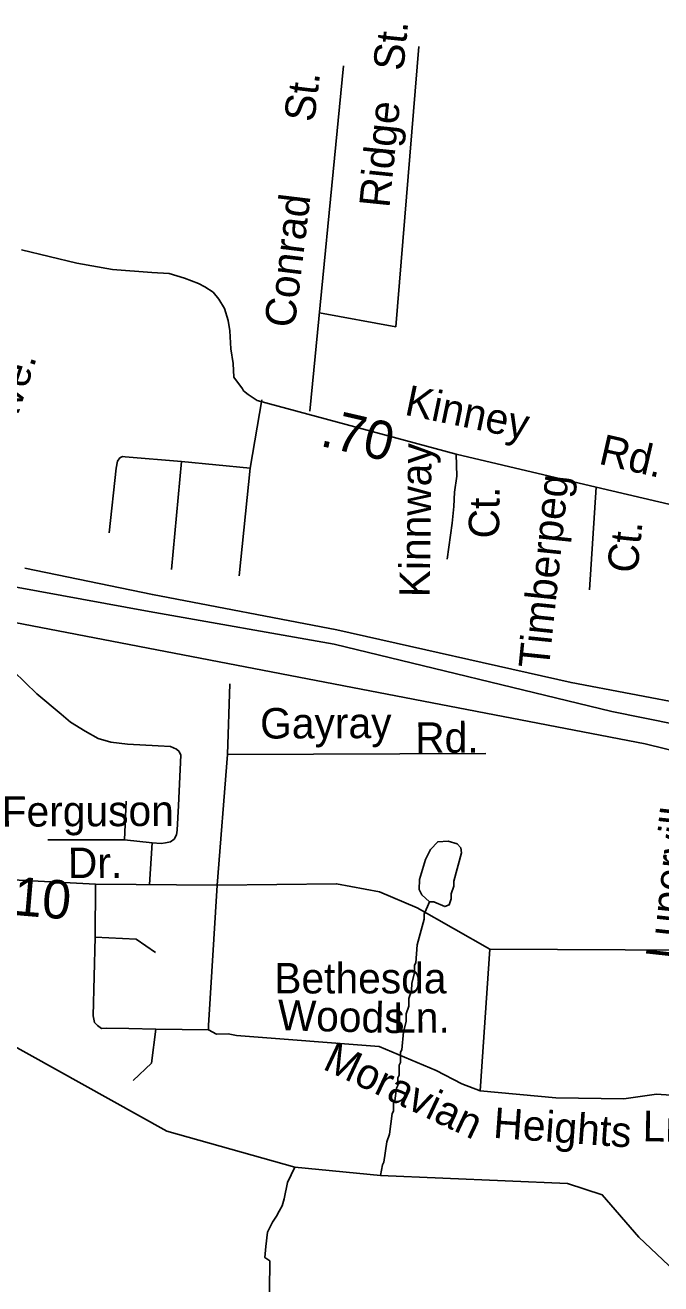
# Model space of a CAD drawing. Extents: x 1547597 to 1699558, y 810033 to 920809.
# Drawn here: x 1591291 to 1593272, y 847300 to 851225 of the extents above; entities that cross this region are included whole.
import ezdxf

# ---------------------------------------------------------------- set-up
doc = ezdxf.new("R2010")
doc.units = 0
for name, color, linetype in [('Exist Boundary Political City Limit New', 7, 'Continuous'), ('Exist Hydrographic Misc Water Feature', 7, 'Continuous'), ('Exist Road Non-System Type 51', 7, 'Continuous'), ('Exist Road Non-System Type 51 Label', 7, 'Continuous'), ('Exist Road Primary US Divided Attributed', 7, 'Continuous'), ('Exist Road Secondary Mileage Hundredths English Label', 7, 'Continuous'), ('Exist Road Secondary Type 51 Attributed', 7, 'Continuous'), ('Exist Road Secondary Type 51 Label', 7, 'Continuous'), ('Map Preparation Boundary City Limit Buffer Line', 7, 'Continuous')]:
    doc.layers.add(name, color=color, linetype=linetype)

msp = doc.modelspace()

# ---------------------------------------------------------------- linework, layer by layer
at = {"layer": 'Exist Boundary Political City Limit New'}
msp.add_lwpolyline([(1596904.9, 847270.3), (1596284, 847806.6), (1595748.2, 848233.1), (1595309.9, 848452.5), (1594414.4, 848690.8), (1593223.6, 848983.5), (1590507.7, 849506.1), (1589412.8, 849462.6)], dxfattribs=at)
at = {"layer": 'Exist Hydrographic Misc Water Feature'}
for points in [[(1592551.1, 848490.7), (1592565, 848490.6), (1592598.8, 848476.1), (1592613, 848481.9), (1592619.1, 848499.9), (1592619.3, 848515.9), (1592627.6, 848539.7), (1592627.8, 848555.7), (1592650.8, 848643.4), (1592649.1, 848659.4), (1592637.2, 848671.6), (1592609.3, 848679.9), (1592577.3, 848678.3), (1592554.9, 848654.6), (1592538.6, 848622.8), (1592519.9, 848561.1), (1592519.5, 848529.1), (1592527.3, 848513), (1592551.1, 848490.7)], [(1592551.1, 848490.7), (1592534.6, 848452.9), (1592534.4, 848436.9), (1592513.4, 848357.3), (1592508.8, 848301.3), (1592504.7, 848293.4), (1592504.4, 848269.4), (1592496.1, 848237.5), (1592495.8, 848213.5), (1592487.5, 848189.6), (1592487.2, 848165.6), (1592478.9, 848141.8), (1592478.7, 848117.8), (1592470.3, 848085.9), (1592465.5, 848030), (1592461.5, 848022.1), (1592461.1, 847990.1), (1592457, 847982.1), (1592456.6, 847950.1), (1592452.5, 847942.2), (1592452.3, 847918.2), (1592448.2, 847910.3), (1592443.7, 847870.4), (1592439.6, 847862.4), (1592439.3, 847838.4), (1592435.2, 847830.5), (1592426.5, 847766.6), (1592418.2, 847742.7), (1592409.5, 847678.9), (1592405.4, 847670.9), (1592399.1, 847637.2)], [(1593705.8, 847052.8), (1593390, 847269.6), (1593203.6, 847445.6), (1593089.8, 847577.5), (1592981.8, 847612.4), (1592399.1, 847637.2), (1592131.3, 847663.1), (1591732.4, 847775.4), (1591129.6, 848111.4)], [(1592032.8, 847046.5), (1592034.2, 847067.8), (1592038.3, 847075.8), (1592038.7, 847107.8), (1592042.8, 847115.7), (1592043.2, 847147.7), (1592047.3, 847155.7), (1592047.5, 847179.7), (1592051.6, 847187.6), (1592053.9, 847371.5), (1592038.6, 847381.7), (1592041.5, 847416), (1592046.4, 847460.7), (1592062.7, 847492.4), (1592074.5, 847511), (1592082.7, 847526.9), (1592092.8, 847543.1), (1592098.5, 847564.5), (1592108.5, 847615.9), (1592131.3, 847663.1)]]:
    msp.add_lwpolyline(points, dxfattribs=at)
at = {"layer": 'Exist Road Non-System Type 51'}
for p, q in [((1592446.2, 850284.4), (1592518.5, 851158.7)), ((1592283.5, 851098.4), (1592178.9, 850020.8)), ((1592446.2, 850284.4), (1592208.7, 850328.1)), ((1592029.4, 850056.7), (1591992.8, 849843.5)), ((1591778.8, 849864.5), (1591747.6, 849527.1)), ((1591992.8, 849843.5), (1591778.8, 849864.5)), ((1591992.8, 849843.5), (1591958.4, 849507.7)), ((1593070.6, 849783.9), (1593050.1, 849463.6)), ((1591921.7, 848950.6), (1591929, 849170.8)), ((1592739.9, 848343.9), (1592709.7, 847901.5))]:
    msp.add_line(p, q, dxfattribs=at)
for points in [[(1591778.8, 849864.5), (1591603, 849879), (1591595, 849879.2), (1591586.9, 849875.3), (1591578.7, 849865.5), (1591574.5, 849843.6), (1591553.6, 849641.7)], [(1592634.5, 849887.4), (1592636.4, 849818.5), (1592628.9, 849768.2), (1592626.8, 849723.7), (1592622.5, 849672), (1592606.6, 849559.6)], [(1591687.5, 848675.3), (1591714.8, 848673.1), (1591728.5, 848675.3), (1591744.4, 848677.6), (1591755.7, 848686.7), (1591762.6, 848700.4), (1591764.8, 848714), (1591769.4, 848791.4), (1591776.2, 848948.4), (1591771.7, 848959.7), (1591762.6, 848966.6), (1591744.4, 848975.7), (1591705.7, 848977.9), (1591610.2, 848982.5), (1591557.9, 848989.3), (1591519.3, 849000.7), (1591478.3, 849023.5), (1591432.8, 849050.8), (1591403.3, 849075.8), (1591328.2, 849139.5), (1591255.5, 849210)], [(1591889.9, 848543.4), (1591921.7, 848950.6), (1592727.4, 848953.7)], [(1591601.1, 848684.4), (1591605.7, 848805)], [(1591601.1, 848684.4), (1591362.3, 848684.4)], [(1591687.5, 848675.3), (1591601.1, 848684.4)], [(1591678.4, 848544.7), (1591687.5, 848675.3)], [(1591510.7, 848545.8), (1591509.1, 848381.1)], [(1591889.9, 848543.4), (1591862.6, 848105.6), (1591862.6, 848091.9), (1591887.6, 848078.3), (1591924.5, 848078.9), (1591950.4, 848074.5), (1592394.1, 848039.9)], [(1591509.1, 848381.1), (1591502.8, 848135), (1591507.5, 848114.6), (1591516.9, 848105.2), (1591529.5, 848095.8), (1591545.2, 848097.3), (1591614.1, 848095.8), (1591698.7, 848094.2)], [(1591509.1, 848381.1), (1591637.6, 848374.9), (1591697.1, 848332.5)], [(1591698.7, 848094.2), (1591684.6, 847987.6), (1591628.2, 847934.3)], [(1591698.7, 848094.2), (1591862.6, 848091.9)], [(1592709.7, 847901.5), (1592652, 847923.5), (1592572.4, 847964.7), (1592394.1, 848039.9)], [(1593483.1, 847875.6), (1593258.8, 847891.2), (1593157.2, 847877), (1592944.7, 847879.4), (1592709.7, 847901.5)]]:
    msp.add_lwpolyline(points, dxfattribs=at)
at = {"layer": 'Exist Road Primary US Divided Attributed'}
for points in [[(1590638.9, 849586.4), (1591678, 849396.8), (1592254.3, 849294.4), (1593119.7, 849084.6), (1593824, 848941.9), (1594286.9, 848867.3), (1594656.2, 848811), (1595128.1, 848723.1), (1595435.7, 848659.4), (1595944.6, 848547.4), (1596390, 848470.5), (1596495.3, 848448.6)], [(1596506.7, 848509.8), (1596372.9, 848534), (1596223.7, 848560.3), (1595962.3, 848607.8), (1595714.7, 848662.1), (1595389.3, 848736.9), (1595059.2, 848790.9), (1594838.5, 848830.9), (1594539.5, 848885.9), (1594246.7, 848937.3), (1593923.6, 848997.9), (1593737.1, 849034), (1592992.5, 849174.6), (1592262.7, 849338.8), (1591688, 849449.1), (1591290.1, 849531.1)]]:
    msp.add_lwpolyline(points, dxfattribs=at)
at = {"layer": 'Exist Road Secondary Type 51 Attributed'}
for points in [[(1591279.6, 850524.1), (1591452.6, 850482.1), (1591563.8, 850463.3), (1591686.6, 850453.2), (1591739.8, 850450.2), (1591787.5, 850435.5), (1591831.4, 850418.8), (1591851.2, 850408.6), (1591876.9, 850392.2), (1591894.7, 850369.9), (1591912.3, 850341.7), (1591923.8, 850303.4), (1591929.3, 850271.3), (1591932.4, 850215.4), (1591939.8, 850169.2), (1591941.2, 850127), (1591969.1, 850090.4), (1591972.3, 850084.8), (1591986.7, 850073.2), (1592014.3, 850054.5), (1592634.5, 849887.4), (1593070.6, 849783.9), (1593461.3, 849692.6)], [(1590993.6, 848572.6), (1591510.7, 848545.8), (1591889.9, 848543.4), (1592262.1, 848547.6), (1592395.8, 848522.5), (1592512.7, 848472.4), (1592739.9, 848343.9), (1593372.1, 848340.6), (1594984, 848241.4)]]:
    msp.add_lwpolyline(points, dxfattribs=at)
at = {"layer": 'Map Preparation Boundary City Limit Buffer Line'}
msp.add_lwpolyline([(1596904.9, 847270.3), (1596284, 847806.6), (1595748.2, 848233.1), (1595309.9, 848452.5), (1594414.4, 848690.8), (1593223.6, 848983.5), (1590507.7, 849506.1), (1589412.8, 849462.6)], dxfattribs=at)

# ---------------------------------------------------------------- texts
at = {"layer": 'Exist Road Non-System Type 51 Label'}
for s, rotation, p in [('St.', 84.1973, (1592469.8, 851080.2)), ('St.', 83.0766, (1592192.2, 850920.4)), ('Ridge', 84.1973, (1592426.4, 850653)), ('Conrad', 83.0766, (1592130.7, 850278.3)), ('Ave.', 71.7839, (1591249, 849947.2)), ('Kinnway', 89.2551, (1592552.2, 849440.3)), ('Timberpeg', 84.0792, (1592923.2, 849215)), ('Ct.', 89.2551, (1592768.2, 849623.5)), ('Ct.', 84.0792, (1593199.1, 849513.3)), ('Gayray', 0.2324, (1592023.8, 849000.1)), ('Rd.', 0.2324, (1592507.1, 848955.4)), ('Luperville', 83.8524, (1593319.5, 848309.5)), ('Ferguson', 0.2987, (1591218.3, 848725.1)), ('Dr.', 0.2944, (1591424.7, 848564.9)), ('Bethesda', 0.0147, (1592067.7, 848205.3)), ('Woods', 358.6039, (1592077.5, 848090.8)), ('Ln.', 0.3375, (1592438.2, 848082.4)), ('Moravian', 334.7401, (1592215.1, 847971.3)), ('Heights', 355.931, (1592748.1, 847755.3)), ('Ln.', 358.9243, (1593215.1, 847744.7))]:
    msp.add_text(s, height=95, rotation=rotation, dxfattribs=at).set_placement(p)
at = {"layer": 'Exist Road Secondary Mileage Hundredths English Label'}
for s, rotation, p in [('.70', 347.0316, (1592207, 849913.5)), ('1.10', 355.1763, (1591118, 848461.7))]:
    msp.add_text(s, height=120, rotation=rotation, dxfattribs=at).set_placement(p)
at = {"layer": 'Exist Road Secondary Type 51 Label'}
for s, rotation, p in [('Kinney', 348.2633, (1592470.4, 850010.5)), ('Rd.', 347.0316, (1593075.4, 849857.5))]:
    msp.add_text(s, height=95, rotation=rotation, dxfattribs=at).set_placement(p)

doc.saveas('drawing.dxf')
